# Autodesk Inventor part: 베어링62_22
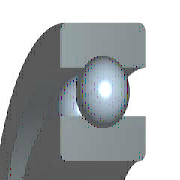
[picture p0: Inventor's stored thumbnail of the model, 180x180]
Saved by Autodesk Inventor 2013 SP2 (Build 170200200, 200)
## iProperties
Created: 2009-02
Part Number: 베어링62_22
Material: 강, 연강
Description: 깊은 그루브 볼 베어링
Document SubType Name: Modeling
Standard: KS B 2023
Designer: KYOUNG IL JANG
Standards Organization: KS
Language: ko-KR
Size Designation: 62/22 - 22 x 50 x 14
Categories: <MemberInstance><Categories><Category DisplayName="샤프트 부품" InternalName="7f7aeb1f-a693-4053-b835-cee3144e0d98" Mnemonic="SHFT"><Category DisplayName="베어링" Inter
Density: 1 g/cm^3
IsCustomPart: 0
Author: KYOUNG IL JANG
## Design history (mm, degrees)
sketch "스케치" dims "d0" = 7.28 (= -0.26 x WD + 0.26 x BD)
  geometry: L1 (3.36, 18)-(10.64, 18); L2 (7, 18)-(7, 14.36); L3 (7, 18)-(7, 21.64); L4 (4.295, 15.564)-(0, 15.564); L5 (0, 11)-(14, 11); L6 (4.295, 20.436)-(0, 20.436); L7 (0, 25)-(14, 25); L8 (14, 11)-(14, 15.564); L9 (9.705, 15.564)-(14, 15.564); L10 (9.705, 20.436)-(14, 20.436); L11 (14, 25)-(14, 20.436); L12 (-1.4, 0)-(8.4, 0) reference; L13 (0, -0.3)-(0, 5.3) reference
  constraints: 22 end point, 4 point on line, 2 collinear, 2 perpendicular, 2 symmetric about line, 1 midpoint, 1 parallel, 14 other
  dimensions: "d9" = 22 diameter of L5 L12 (= WD); "d11" = 50 diameter of L7 L12 (= BD); "d12" = 14 distance between parallel lines of L8 L13 (= KB); "d13" = 31.128 diameter of L9 L12 (= 0.326 x BD + 0.674 x WD)
revolve "본체" stored, may be unused: angle "d6" = 90 deg
revolve "볼" stored, may be unused: angle "d7" = 90 deg
pattern_circular "IDS_ARRAYBALL[SIMPL:T]" dims angle "d3" = 360 deg
body "Solid1"
fillet "모깎기1" dims "d1" = 1 (= KRS)
other parameters: "WD" = 22 [user parameter; used in 5 equation terms], "BD" = 50 [user parameter; used in 5 equation terms], "KB" = 14 [user parameter; used in 1 equation term], "KRS" = 1 [user parameter; used in 1 equation term], "d4" = 0, "d5" = 0, "d8" = 0, "d14" = 0, "d15" = 0, "BBA" = 0 [user parameter], "BC0" = 7154000 [user parameter], "BC" = 1.2233e+07 [user parameter], "BR" = 25 (= 0.5 x BD) [user parameter], "WR" = 11 (= 0.5 x WD) [user parameter]
